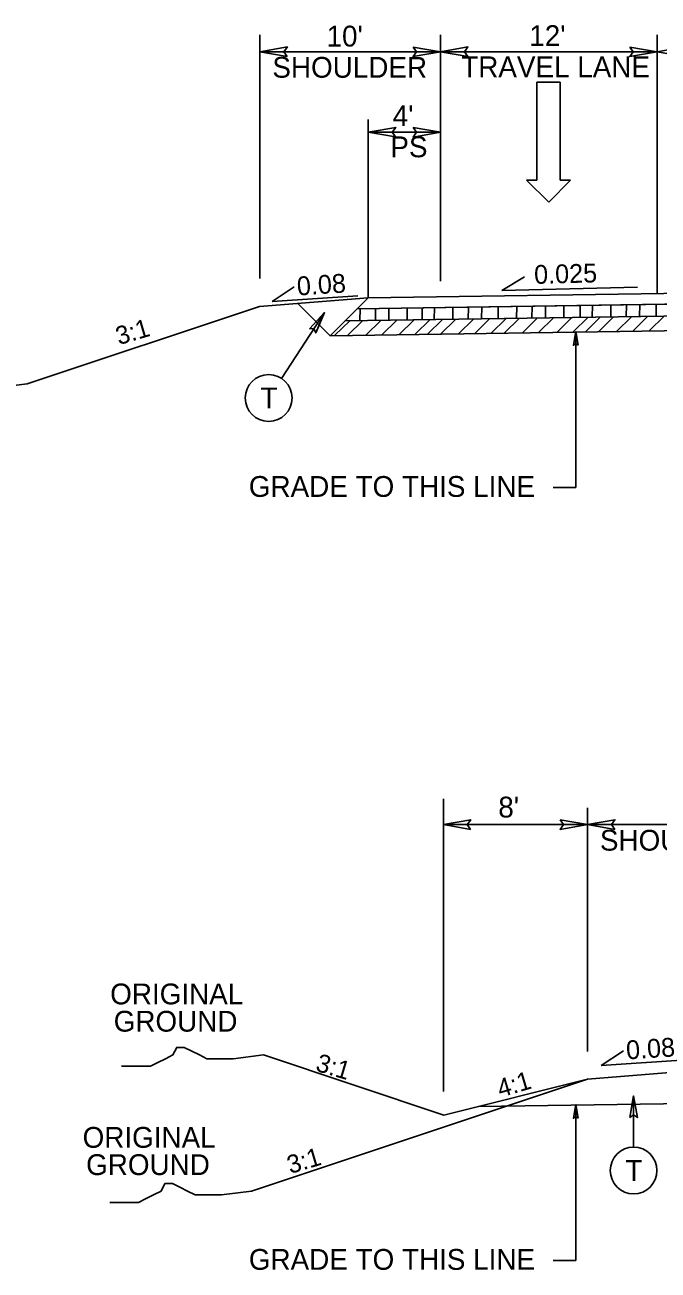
# Model space of a CAD drawing. Extents: x 2176156 to 2177167, y 76401 to 76644.
# Drawn here: x 2176765.8 to 2176800.9, y 76511.1 to 76580.1 of the extents above; entities that cross this region are included whole.
import ezdxf

# ---------------------------------------------------------------- set-up
doc = ezdxf.new("R2010")
doc.units = 0
for name, color, linetype in [('Exist Building', 7, 'Continuous'), ('Exist Roads Curbs', 7, 'Continuous'), ('Exist Roads EOP Other', 7, 'Continuous'), ('Exist Roads Soil', 7, 'Continuous'), ('Exist Structure Minor Culvert Topo', 7, 'Continuous'), ('Exist Structure Minor Drop Inlet', 7, 'Continuous'), ('Exist Utilities Other Pole CELL', 7, 'Continuous'), ('Model Boundary Lines Text', 7, 'Continuous'), ('Old_Level_1', 7, 'Continuous'), ('Old_Level_3', 7, 'Continuous'), ('Prop North Arrow NAD83 for Plan Sheets CELL', 7, 'Continuous')]:
    doc.layers.add(name, color=color, linetype=linetype)

msp = doc.modelspace()

# ---------------------------------------------------------------- linework, layer by layer
at = {"layer": 'Exist Building'}
for p, q in [((2176782.727, 76562.893), (2176780.935, 76564.685)), ((2176782.727, 76562.893), (2176812.069, 76563.329)), ((2176790.942, 76520.175), (2176812.069, 76520.489))]:
    msp.add_line(p, q, dxfattribs=at)
at = {"layer": 'Exist Roads Curbs'}
for p, q in [((2176821.519, 76565.542), (2176784.844, 76564.997)), ((2176812.069, 76565.402), (2176784.844, 76564.997)), ((2176784.844, 76564.997), (2176784.236, 76564.393))]:
    msp.add_line(p, q, dxfattribs=at)
for points in [[(2176784.236, 76564.393), (2176802.673, 76564.667), (2176803.416, 76564.679)], [(2176765.95, 76560.229), (2176764.279, 76560.021), (2176763.862, 76560.021), (2176763.234, 76560.021), (2176762.817, 76560.021), (2176762.399, 76560.229), (2176761.981, 76560.438), (2176761.564, 76560.648), (2176761.146, 76560.648), (2176760.936, 76560.229), (2176760.519, 76560.021), (2176760.101, 76559.811), (2176759.683, 76559.603), (2176759.266, 76559.603), (2176758.848, 76559.603), (2176758.43, 76559.603), (2176758.091, 76559.603)], [(2176779.037, 76523.032), (2176777.366, 76522.824), (2176776.948, 76522.824), (2176776.321, 76522.824), (2176775.904, 76522.824), (2176775.486, 76523.032), (2176775.068, 76523.242), (2176774.651, 76523.451), (2176774.233, 76523.451), (2176774.023, 76523.032), (2176773.606, 76522.824), (2176773.188, 76522.614), (2176772.77, 76522.406), (2176772.353, 76522.406), (2176771.935, 76522.406), (2176771.517, 76522.406), (2176771.178, 76522.406)], [(2176778.379, 76515.483), (2176776.708, 76515.275), (2176776.291, 76515.275), (2176775.663, 76515.275), (2176775.246, 76515.275), (2176774.828, 76515.483), (2176774.41, 76515.693), (2176773.993, 76515.903), (2176773.575, 76515.903), (2176773.365, 76515.483), (2176772.948, 76515.275), (2176772.53, 76515.066), (2176772.112, 76514.858), (2176771.695, 76514.858), (2176771.277, 76514.858), (2176770.859, 76514.858), (2176770.52, 76514.858)]]:
    msp.add_lwpolyline(points, dxfattribs=at)
at = {"layer": 'Exist Roads EOP Other'}
for p, q in [((2176765.95, 76560.229), (2176778.809, 76564.515)), ((2176784.844, 76564.998), (2176778.809, 76564.515)), ((2176789.037, 76519.699), (2176779.037, 76523.032)), ((2176806.989, 76522.486), (2176796.989, 76521.686)), ((2176778.379, 76515.483), (2176796.989, 76521.686)), ((2176789.037, 76519.699), (2176796.989, 76521.686))]:
    msp.add_line(p, q, dxfattribs=at)
at = {"layer": 'Exist Roads Soil'}
for p, q in [((2176784.844, 76564.998), (2176782.727, 76562.893)), ((2176812.069, 76564.807), (2176784.236, 76564.393)), ((2176812.057, 76564.136), (2176783.55, 76563.711))]:
    msp.add_line(p, q, dxfattribs=at)
at = {"layer": 'Exist Structure Minor Drop Inlet'}
for p, q in [((2176794.184, 76571.517), (2176794.184, 76576.949)), ((2176794.184, 76576.949), (2176795.464, 76576.949)), ((2176795.464, 76576.949), (2176795.464, 76571.517)), ((2176794.844, 76570.295), (2176793.602, 76571.517)), ((2176793.602, 76571.517), (2176794.184, 76571.517)), ((2176796.046, 76571.517), (2176794.844, 76570.295)), ((2176795.464, 76571.517), (2176796.046, 76571.517))]:
    msp.add_line(p, q, dxfattribs=at)
at = {"layer": 'Exist Utilities Other Pole CELL'}
for p, q in [((2176792.249, 76565.394), (2176793.505, 76566.164)), ((2176779.513, 76564.789), (2176780.737, 76565.608)), ((2176792.249, 76565.394), (2176799.753, 76565.59)), ((2176779.513, 76564.789), (2176784.259, 76565.103)), ((2176797.748, 76522.448), (2176798.973, 76523.267)), ((2176797.748, 76522.448), (2176802.494, 76522.761))]:
    msp.add_line(p, q, dxfattribs=at)
at = {"layer": 'Model Boundary Lines Text'}
for p, q in [((2176790.376, 76563.813), (2176790.386, 76564.485)), ((2176791.12, 76563.826), (2176791.129, 76564.496)), ((2176792.035, 76563.839), (2176792.045, 76564.509)), ((2176793.053, 76563.853), (2176793.063, 76564.524)), ((2176793.911, 76563.866), (2176793.921, 76564.537)), ((2176794.654, 76563.878), (2176794.664, 76564.548)), ((2176795.672, 76563.892), (2176795.682, 76564.563)), ((2176796.573, 76563.907), (2176796.583, 76564.577)), ((2176797.252, 76563.917), (2176797.262, 76564.587)), ((2176798.27, 76563.931), (2176798.28, 76564.602)), ((2176799.128, 76563.943), (2176799.138, 76564.615)), ((2176799.872, 76563.956), (2176799.881, 76564.626)), ((2176800.787, 76563.97), (2176800.797, 76564.64)), ((2176784.376, 76563.724), (2176784.386, 76564.395)), ((2176785.234, 76563.736), (2176785.244, 76564.408)), ((2176785.978, 76563.749), (2176785.987, 76564.419)), ((2176786.996, 76563.763), (2176787.005, 76564.434)), ((2176787.441, 76562.973), (2176788.276, 76563.792)), ((2176787.821, 76563.777), (2176787.831, 76564.447)), ((2176788.12, 76562.984), (2176788.955, 76563.802)), ((2176788.501, 76563.787), (2176788.51, 76564.457)), ((2176788.856, 76563.004), (2176789.67, 76563.802)), ((2176789.518, 76563.8), (2176789.528, 76564.472)), ((2176789.846, 76563.004), (2176790.672, 76563.814)), ((2176790.739, 76563.023), (2176791.574, 76563.841)), ((2176791.655, 76563.036), (2176792.49, 76563.855)), ((2176792.391, 76563.057), (2176793.205, 76563.855)), ((2176793.38, 76563.057), (2176794.207, 76563.867)), ((2176794.274, 76563.075), (2176795.109, 76563.894)), ((2176795.299, 76563.085), (2176796.126, 76563.896)), ((2176796.193, 76563.104), (2176797.028, 76563.923)), ((2176796.872, 76563.114), (2176797.707, 76563.933)), ((2176797.608, 76563.135), (2176798.422, 76563.933)), ((2176798.597, 76563.135), (2176799.424, 76563.945)), ((2176799.491, 76563.153), (2176800.326, 76563.972)), ((2176800.407, 76563.166), (2176801.242, 76563.985)), ((2176782.978, 76562.907), (2176783.813, 76563.726)), ((2176783.714, 76562.928), (2176784.528, 76563.726)), ((2176784.704, 76562.928), (2176785.53, 76563.738)), ((2176785.597, 76562.946), (2176786.432, 76563.765)), ((2176786.547, 76562.955), (2176787.374, 76563.765))]:
    msp.add_line(p, q, dxfattribs=at)
at = {"layer": 'Old_Level_1'}
for points in [[(2176780.353, 76578.375), (2176778.844, 76578.635), (2176780.362, 76578.904), (2176780.169, 76578.635)], [(2176787.334, 76578.895), (2176788.844, 76578.635), (2176787.326, 76578.367), (2176787.518, 76578.635)], [(2176790.353, 76578.375), (2176788.844, 76578.635), (2176790.362, 76578.904), (2176790.169, 76578.635)], [(2176799.334, 76578.895), (2176800.844, 76578.635), (2176799.326, 76578.367), (2176799.518, 76578.635)], [(2176802.353, 76578.375), (2176800.844, 76578.635), (2176802.362, 76578.904), (2176802.169, 76578.635)], [(2176786.353, 76573.915), (2176784.844, 76574.175), (2176786.362, 76574.443), (2176786.169, 76574.175)], [(2176787.334, 76574.435), (2176788.844, 76574.175), (2176787.326, 76573.907), (2176787.518, 76574.175)], [(2176796.473, 76562.366), (2176796.343, 76563.121), (2176796.209, 76562.362), (2176796.343, 76562.458)], [(2176790.511, 76535.535), (2176789.001, 76535.795), (2176790.519, 76536.063), (2176790.327, 76535.795)], [(2176795.479, 76536.055), (2176796.989, 76535.795), (2176795.471, 76535.527), (2176795.664, 76535.795)], [(2176798.498, 76535.535), (2176796.989, 76535.795), (2176798.507, 76536.063), (2176798.314, 76535.795)], [(2176796.473, 76519.526), (2176796.343, 76520.281), (2176796.209, 76519.522), (2176796.343, 76519.618)]]:
    msp.add_lwpolyline(points, close=True, dxfattribs=at)
at = {"layer": 'Old_Level_3'}
for p, q in [((2176778.844, 76566.065), (2176778.844, 76579.563)), ((2176788.844, 76565.914), (2176788.844, 76579.563)), ((2176800.844, 76565.235), (2176800.844, 76579.563)), ((2176788.844, 76578.635), (2176778.844, 76578.635)), ((2176800.844, 76578.635), (2176788.95, 76578.635)), ((2176784.844, 76564.997), (2176784.844, 76574.885)), ((2176788.844, 76574.175), (2176784.844, 76574.175)), ((2176796.343, 76563.121), (2176796.343, 76554.486)), ((2176795.082, 76554.486), (2176796.343, 76554.486)), ((2176789.001, 76520.998), (2176789.001, 76537.229)), ((2176796.989, 76523.224), (2176796.989, 76536.723)), ((2176796.989, 76535.795), (2176789.001, 76535.795)), ((2176806.989, 76535.795), (2176796.989, 76535.795)), ((2176796.343, 76520.281), (2176796.343, 76511.645)), ((2176795.082, 76511.645), (2176796.343, 76511.645))]:
    msp.add_line(p, q, dxfattribs=at)
at = {"layer": 'Prop North Arrow NAD83 for Plan Sheets CELL'}
for p, q in [((2176780.034, 76560.53), (2176782.409, 76564.175)), ((2176799.54, 76517.921), (2176799.54, 76520.762))]:
    msp.add_line(p, q, dxfattribs=at)
for points in [[(2176781.581, 76563.283), (2176782.409, 76564.175), (2176781.929, 76563.048), (2176781.834, 76563.293)], [(2176799.333, 76519.562), (2176799.54, 76520.762), (2176799.753, 76519.556), (2176799.54, 76519.709)]]:
    msp.add_lwpolyline(points, close=True, dxfattribs=at)
for centre in [(2176779.326, 76559.444), (2176799.54, 76516.625)]:
    msp.add_circle(centre, 1.296, dxfattribs=at)

# ---------------------------------------------------------------- texts
at = {"layer": 'Exist Roads Curbs'}
for s, rotation, p in [('3:1', 16.46494, (2176771.027, 76562.368)), ('3:1', 343.53506, (2176781.872, 76522.165)), ('4:1', 16.46494, (2176792.158, 76520.659)), ('3:1', 16.46494, (2176780.519, 76516.429))]:
    msp.add_text(s, height=1.0064, rotation=rotation, dxfattribs=at).set_placement(p)
at = {"layer": 'Exist Structure Minor Culvert Topo'}
for s, height, p in [("10' ", 1.1533, (2176782.531, 76578.924)), ("12'", 1.1533, (2176793.762, 76578.951)), ('SHOULDER', 1.1533, (2176779.53, 76577.194)), ('TRAVEL LANE', 1.15334, (2176789.992, 76577.221)), ("4' ", 1.1533, (2176786.196, 76574.516)), ('PS', 1.1533, (2176786.066, 76572.786)), ('GRADE TO THIS LINE', 1.15334, (2176778.227, 76553.962)), ("8'", 1.1533, (2176792.046, 76536.19)), ('SHOULDER', 1.1533, (2176797.675, 76534.354)), ('ORIGINAL', 1.1533, (2176770.546, 76525.834)), ('GROUND', 1.1533, (2176770.74, 76524.322)), ('ORIGINAL', 1.1533, (2176769.018, 76517.885)), ('GROUND', 1.1533, (2176769.212, 76516.373)), ('GRADE TO THIS LINE', 1.15334, (2176778.227, 76511.122))]:
    msp.add_text(s, height=height, dxfattribs=at).set_placement(p)
at = {"layer": 'Exist Utilities Other Pole CELL'}
for s, rotation, p in [('0.025', 1.49319, (2176794.043, 76565.763)), ('0.08', 3.78012, (2176780.923, 76565.119)), ('0.08', 3.78012, (2176799.158, 76522.778))]:
    msp.add_text(s, height=1.0429, rotation=rotation, dxfattribs=at).set_placement(p)
at = {"layer": 'Prop North Arrow NAD83 for Plan Sheets CELL'}
for p in [(2176778.869, 76558.864), (2176799.083, 76516.045)]:
    msp.add_text('T', height=1.16, rotation=359.99974, dxfattribs=at).set_placement(p)

doc.saveas('drawing.dxf')
